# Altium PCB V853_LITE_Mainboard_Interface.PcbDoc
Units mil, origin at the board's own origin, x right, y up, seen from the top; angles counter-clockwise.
Board outline 3937.01 x 3385.83 mil, 4 copper layers (Top Layer, GND, PWR, Bottom Layer); 3 components, 131 nets, 196 pads, 0 vias.
Unrouted connection lines stored in the file: 39.
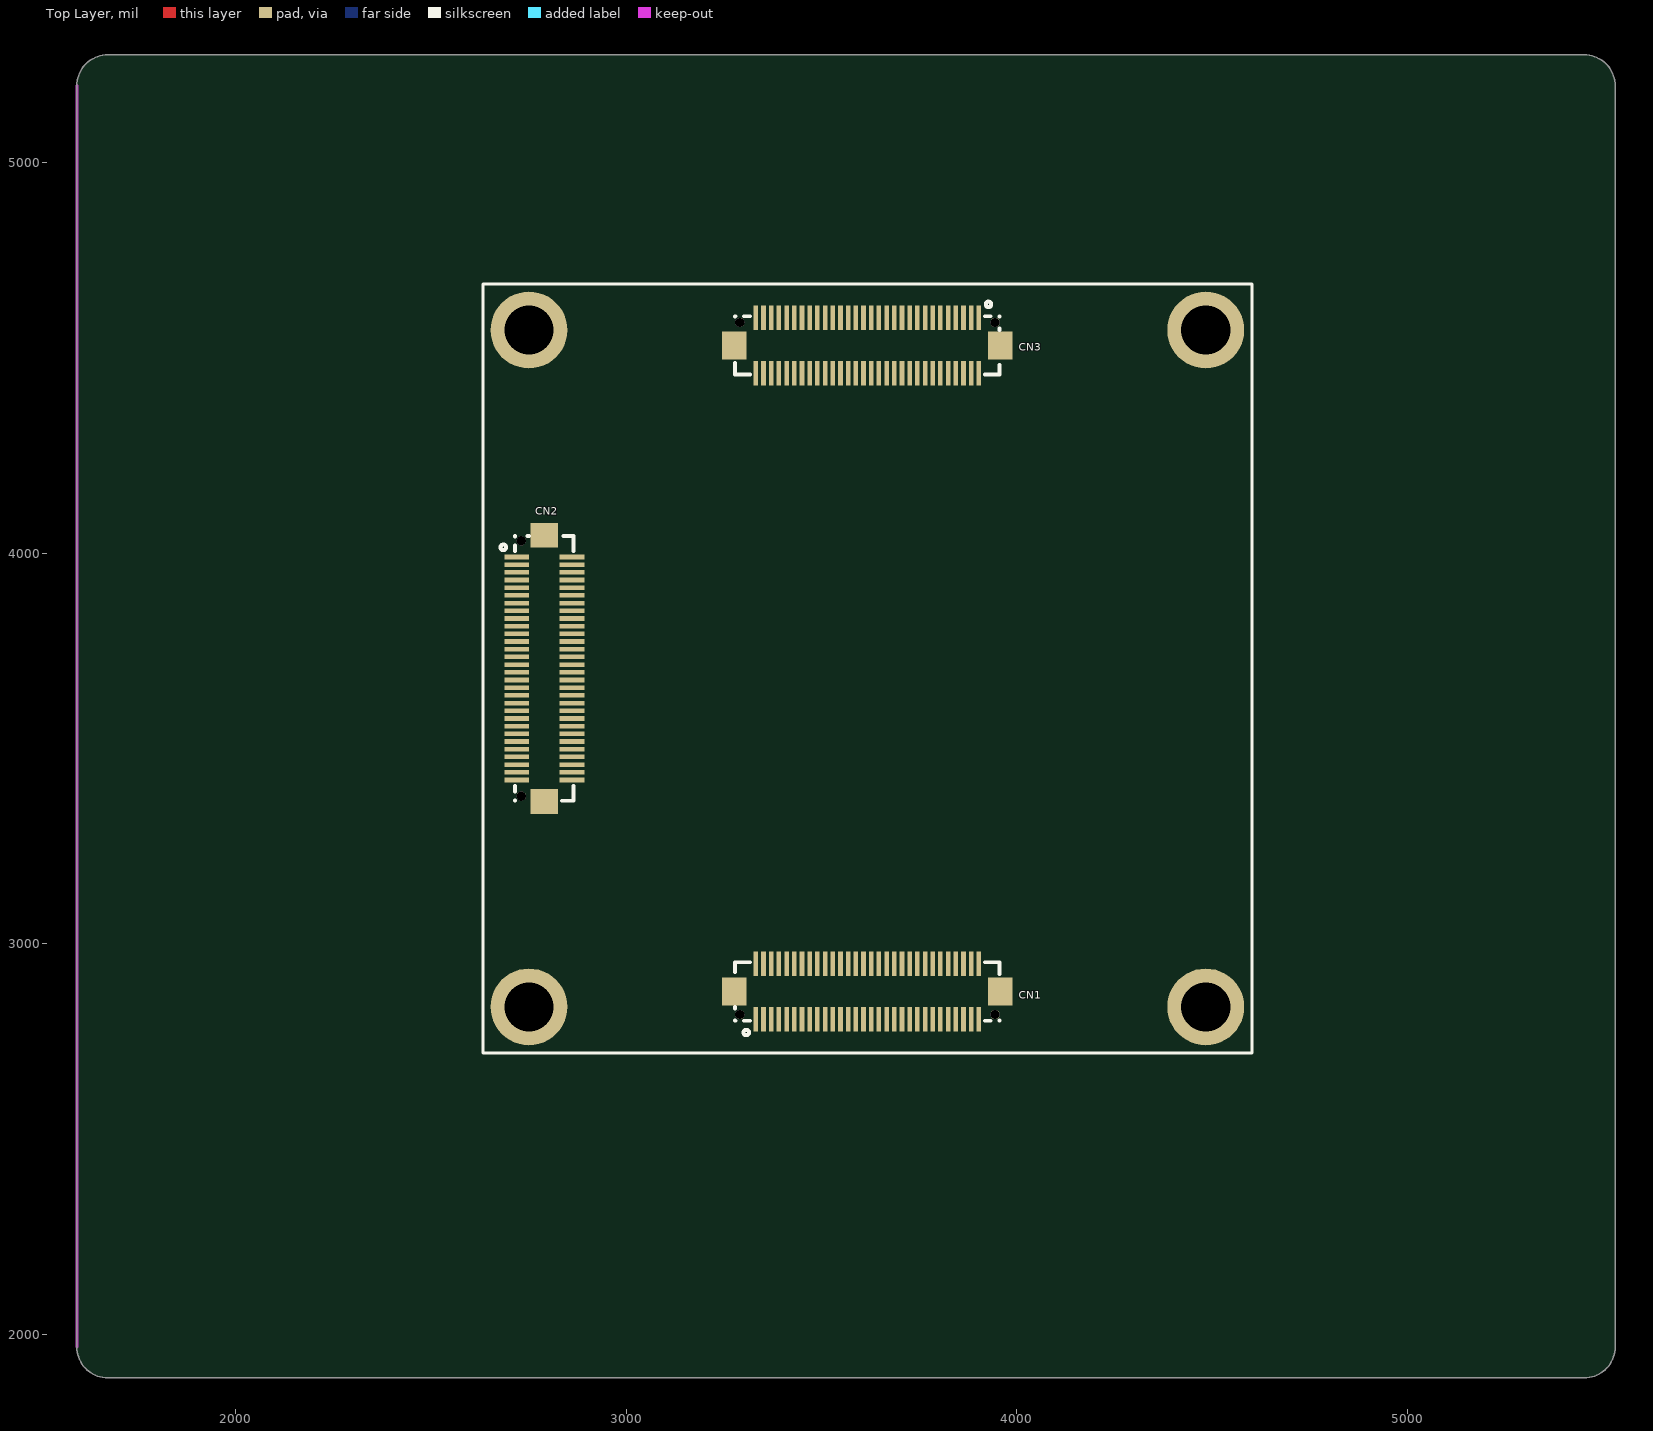
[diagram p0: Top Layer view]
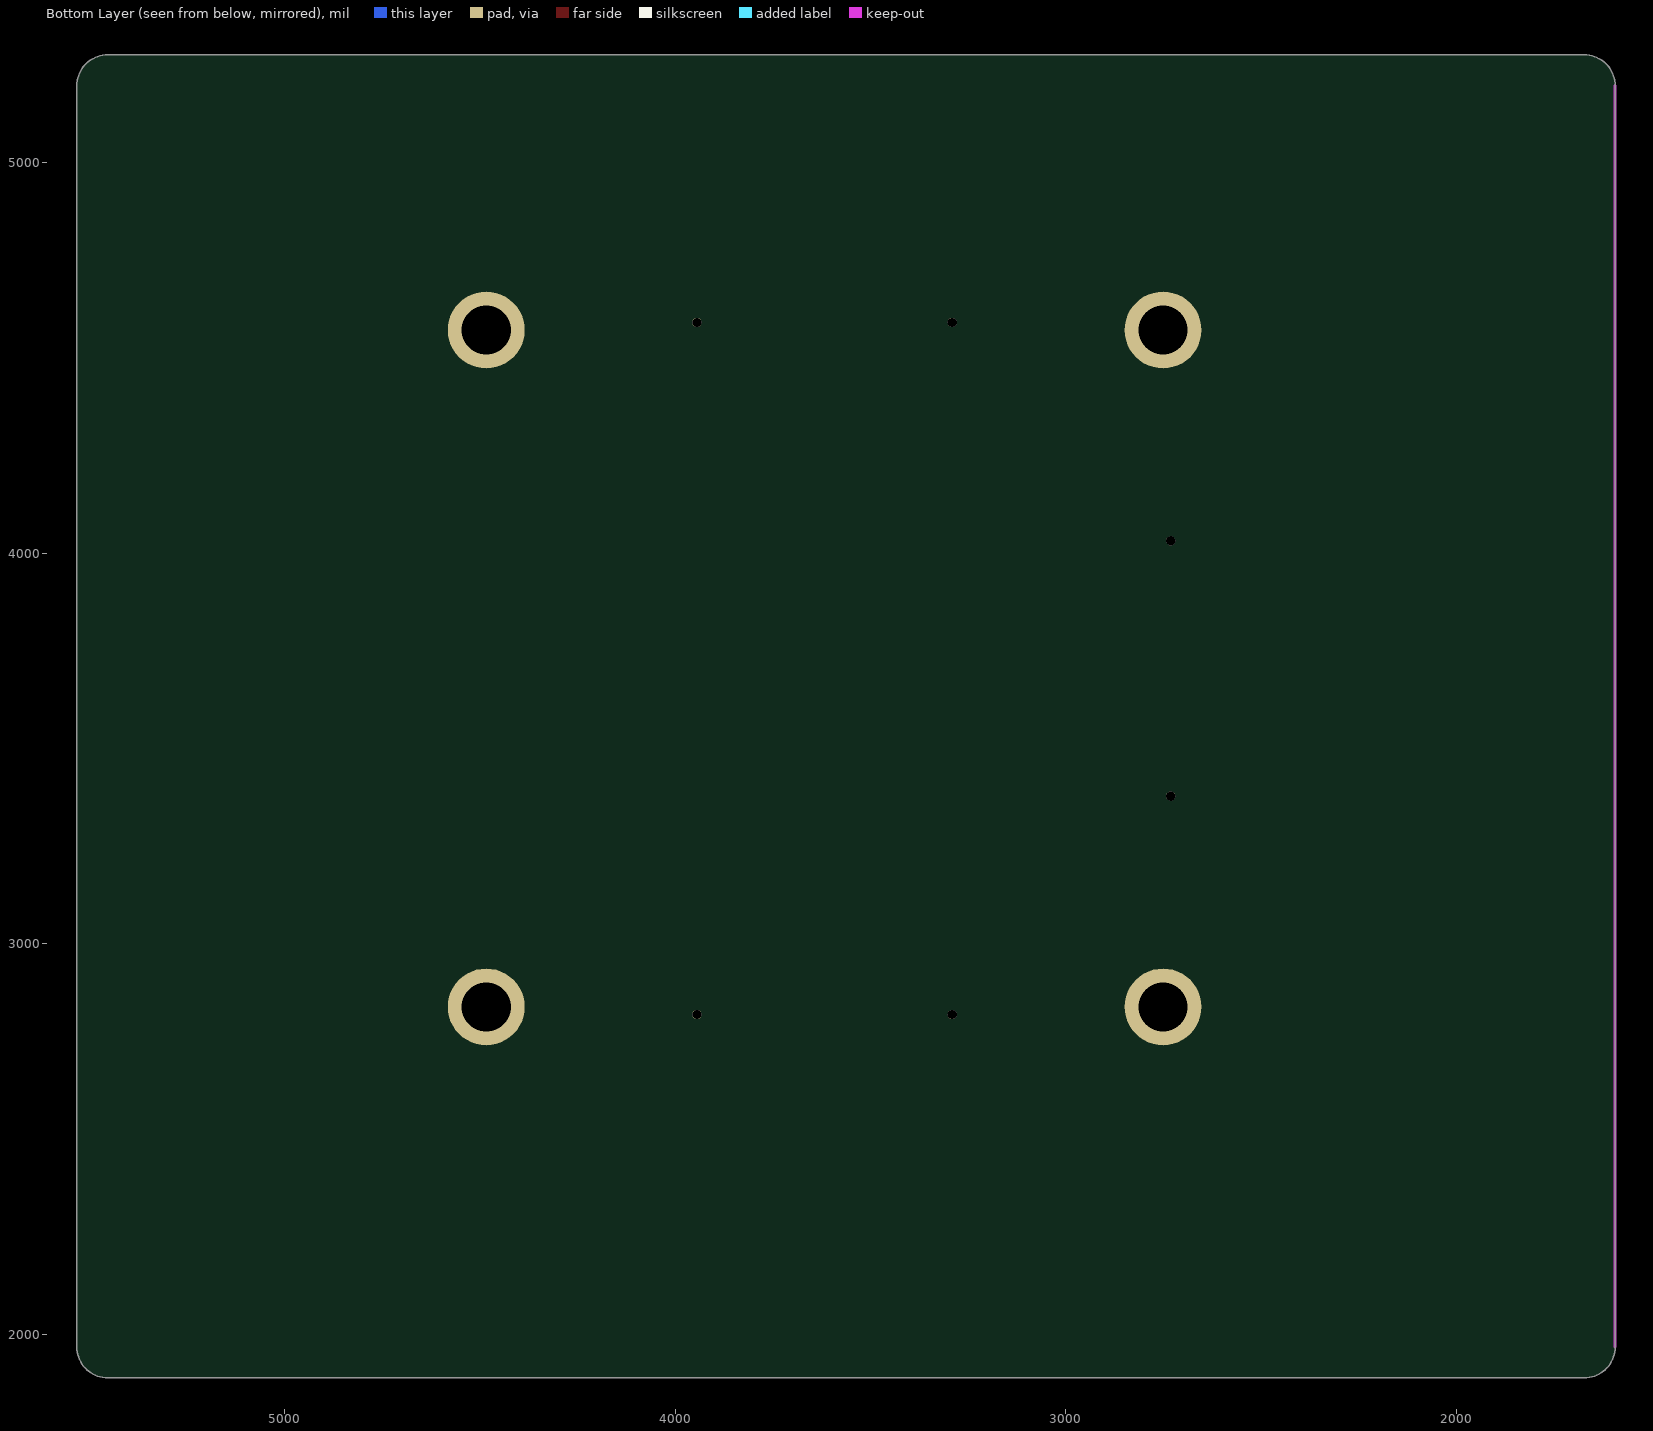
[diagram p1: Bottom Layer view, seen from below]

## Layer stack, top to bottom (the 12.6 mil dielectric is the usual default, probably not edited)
Top Solder: solder mask 0.4, Solder Resist, Dk 3.5
Top Layer: signal copper 1.4
Dielectric1: core 12.6, FR-4, Dk 4.8
GND: signal copper 1.4
Dielectric3: prepreg 12.6, FR-4, Dk 4.8
PWR: signal copper 1.4
Dielectric2: core 12.6, FR-4, Dk 4.8
Bottom Layer: signal copper 1.4
Bottom Solder: solder mask 0.4, Solder Resist, Dk 3.5

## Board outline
1594.49,1968.5 1594.49,5196.85 cw(c1673.23,5196.85) 1673.23,5275.59 5452.76,5275.59 cw(c5452.76,5196.85) 5531.5,5196.85 5531.5,1968.5 cw(c5452.76,1968.5) 5452.76,1889.76 1673.23,1889.76 cw(c1673.23,1968.5)

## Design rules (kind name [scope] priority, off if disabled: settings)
Clearance Clearance_1 [InPolygon] p1: gap=15
Clearance [All] p2: gap=5
ComponentClearance [All] p1 off: gap=10 collisioncheckmode=3 verticalgap=10 showdistances=FALSE
HoleSize [All] p1: absolutevalues=TRUE maxlimit=200 minlimit=1 maxpercent=80.000 minpercent=20.000
MinimumSolderMaskSliver [All] p1 off: minsoldermaskwidth=3
PolygonConnect PolygonConnect_1 [IsVia] p1: connectstyle=Direct reliefconductorwidth=10 reliefentries=4 polygonreliefangle="90 Angle" airgapwidth=10
PolygonConnect [All] p2: connectstyle=Relief reliefconductorwidth=20 reliefentries=4 polygonreliefangle="90 Angle" airgapwidth=20
RoutingVias [All] p1: holewidth=7.87 width=17.72 viastyle="Through Hole" minholewidth=7.87 minwidth=17.72 maxholewidth=7.87 maxwidth=17.72
SilkToSilkClearance [All] p1 off: silktosilkclearance=10
SilkToSolderMaskClearance [IsPad] p1 off: minsilkscreentomaskgap=3 clearancetoexposedcopper=TRUE
SolderMaskExpansion [All] p1: expansion=4
Width [All] p1: maxlimit=100 minlimit=5 preferedwidth=5 minimp=50.000000 maximp=50.000000 favimp=50.000000
25 further rules are at their usual default settings.

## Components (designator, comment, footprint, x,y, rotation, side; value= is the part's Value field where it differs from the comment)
CN1 "" CONN-SMD_60P-P0.50_XKB_X0502FVS-60AS-LPSN 3617.7,2878.38 r0 top locked
CN2 "" CONN-SMD_60P-P0.50_XKB_X0502FVS-60AS-LPSN 2790.93,3705.15 r270 top locked
CN3 "" CONN-SMD_60P-P0.50_XKB_X0502FVS-60AS-LPSN 3617.7,4531.93 r180 top locked

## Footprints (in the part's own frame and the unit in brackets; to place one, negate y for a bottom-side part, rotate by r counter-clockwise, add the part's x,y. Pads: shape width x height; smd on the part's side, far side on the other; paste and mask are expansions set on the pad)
CONN-SMD_60P-P0.50_XKB_X0502FVS-60AS-LPSN [mm]
  rect 0.3x1.6 smd paste+0 mask+0.05: 1(-7.25,-1.8) 2(-7.25,1.8) 3(-6.75,-1.8) 4(-6.75,1.8) 5(-6.25,-1.8) 6(-6.25,1.8) 7(-5.75,-1.8) 8(-5.75,1.8) 9(-5.25,-1.8) 10(-5.25,1.8) 11(-4.75,-1.8) 12(-4.75,1.8) 13(-4.25,-1.8) 14(-4.25,1.8) 15(-3.75,-1.8) 16(-3.75,1.8) 17(-3.25,-1.8) 18(-3.25,1.8) 19(-2.75,-1.8) 20(-2.75,1.8) 21(-2.25,-1.8) 22(-2.25,1.8) 23(-1.75,-1.8) 24(-1.75,1.8) 25(-1.25,-1.8) 26(-1.25,1.8) 27(-0.75,-1.8) 28(-0.75,1.8) 29(-0.25,-1.8) 30(-0.25,1.8) 31(0.25,-1.8) 32(0.25,1.8) 33(0.75,-1.8) 34(0.75,1.8) 35(1.25,-1.8) 36(1.25,1.8) 37(1.75,-1.8) 38(1.75,1.8) 39(2.25,-1.8) 40(2.25,1.8) 41(2.75,-1.8) 42(2.75,1.8) 43(3.25,-1.8) 44(3.25,1.8) 45(3.75,-1.8) 46(3.75,1.8) 47(4.25,-1.8) 48(4.25,1.8) 49(4.75,-1.8) 50(4.75,1.8) 51(5.25,-1.8) 52(5.25,1.8) 53(5.75,-1.8) 54(5.75,1.8) 55(6.25,-1.8) 56(6.25,1.8) 57(6.75,-1.8) 58(6.75,1.8) 59(7.25,-1.8) 60(7.25,1.8)
  rect 1.6x1.8 smd paste+0 mask+0.05: 61(8.65,0) 62(-8.65,0)
  round 0.6 hole 0.6 unplated paste+0: ""(-8.3,-1.5) ""(8.3,-1.5)
  silkscreen extent -8.6,-2.85 8.6,1.9

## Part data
CN1 CN2 CN3: library part X0502FVS-60AS-LPSN

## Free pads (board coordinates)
  round 196.85 hole 125.98: 0(2751.56,2839.01) 0(2751.56,4571.3) 0(4483.85,2839.01) 0(4483.85,4571.3)

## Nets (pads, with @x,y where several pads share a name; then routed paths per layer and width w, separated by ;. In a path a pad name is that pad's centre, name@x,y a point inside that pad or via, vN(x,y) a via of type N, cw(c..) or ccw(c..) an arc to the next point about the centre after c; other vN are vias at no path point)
ACIN: CN3.15 CN3.16 CN3.17 CN3.18 CN3.19 CN3.20
AP_RESET: CN1.55
AP_WAKE_BT_SOC: CN1.13
BT_RST_N_SOC: CN1.10
BT_UART_CTS: CN1.18
BT_UART_RTS: CN1.17
BT_UART_RX: CN1.16
BT_UART_TX: CN1.15
BT_WAKE_AP_SOC: CN1.14
CARD_PWROFF: CN3.34
CLK_FANOUT0: CN1.48
CPUX_TDI: CN3.30
CPUX_TDO: CN3.33
CPUX_TMS: CN3.35
CTP_INT: CN3.39
CTP_RST: CN3.38
CTP_SCL: CN3.43
CTP_SDA: CN3.40
DCDC1: CN1.54 CN1.56 CN1.58 CN1.60
DCXO_RFCLK: CN1.57
EPHY_LINK_LED: CN1.35
EPHY_RXN: CN1.38
EPHY_RXP: CN1.40
EPHY_SPD_LED: CN1.36
EPHY_TXN: CN1.37
EPHY_TXP: CN1.39
FEL: CN1.59
GND: CN1.11 CN1.12 CN1.21 CN1.22 CN1.31 CN1.32 CN1.41 CN1.42 CN2.11 CN2.12 CN2.21 CN2.22 CN2.31 CN2.32 CN2.41 CN2.42 CN3.11 CN3.12 CN3.21 CN3.22 CN3.31 CN3.32 CN3.41 CN3.42
GPADC0: CN3.49
GPADC1: CN3.50
GPADC2: CN3.51
GPADC3: CN3.52
LCD_RST: CN1.9
LINEOUTN: CN3.53
LINEOUTP: CN3.55
MBIAS: CN3.59
MICIN1N: CN3.60
MICIN1P: CN3.58
MICIN2N: CN3.56
MICIN2P: CN3.54
MIPI_CSI_CKN: CN2.25
MIPI_CSI_CKP: CN2.26
MIPI_CSI_D0N: CN2.19
MIPI_CSI_D0P: CN2.20
MIPI_CSI_D1N: CN2.24
MIPI_CSI_D1P: CN2.23
MIPI_CSI_D2N: CN2.18
MIPI_CSI_D2P: CN2.17
MIPI_CSI_D3N: CN2.16
MIPI_CSI_D3P: CN2.15
MIPI_CSI_MCLK0: CN2.10
MIPI_CSI_MCLK1: CN2.9
MIPI_CSI_PWDN0: CN2.3
MIPI_CSI_PWDN1: CN2.1
MIPI_CSI_RSTN0: CN2.4
MIPI_CSI_RSTN1: CN2.2
MIPI_DSI_CKN: CN2.43
MIPI_DSI_CKP: CN2.44
MIPI_DSI_D0N: CN2.37
MIPI_DSI_D0P: CN2.38
MIPI_DSI_D1N: CN2.39
MIPI_DSI_D1P: CN2.40
MIPI_DSI_D2N: CN2.45
MIPI_DSI_D2P: CN2.47
MIPI_DSI_D3N: CN2.48
MIPI_DSI_D3P: CN2.49
MIPIB_CSI_CKN: CN2.14
MIPIB_CSI_CKP: CN2.13
PA14: CN2.8
PA15: CN2.7
PA16: CN2.6
PA17: CN2.5
PA_SHDN: CN3.44
PD0: CN2.36
PD8: CN2.46
PD12: CN2.50
PD13: CN2.51
PD14: CN2.52
PD15: CN2.53
PD16: CN2.54
PD17: CN2.55
PD18: CN2.56
PD19: CN2.57
PD20: CN2.58
PD21: CN2.59
PD22: CN2.60
PE0: CN1.30
PE1: CN1.29
PE2: CN1.28
PE3: CN1.27
PE4: CN1.26
PE5: CN1.25
PE6: CN1.24
PE7: CN1.23
PE8: CN1.20
PE9: CN1.19
PH0: CN3.48
PH1: CN3.47
PH2: CN3.46
PH3: CN3.45
PH9: CN3.37
PH10: CN3.36
PH15: CN3.29
PI0: CN2.29
PI1: CN2.30
PI2: CN2.33
PI3: CN2.34
PI4: CN2.35
PS: CN3.5 CN3.6 CN3.7 CN3.8 CN3.9 CN3.10
PWRON_AXP2101: CN1.53
SDC0_CLK: CN1.4
SDC0_CMD: CN1.5
SDC0_D0: CN1.3
SDC0_D1: CN1.2
SDC0_D2: CN1.7
SDC0_D3: CN1.6
SDC0_DET: CN1.8
TS: CN3.28
TS_NTC: 
USB0_DM: CN2.28
USB0_DP: CN2.27
VBAT: CN3.23 CN3.24 CN3.25 CN3.26
VBAT2: CN3.27
VCC_3V3: 
WL_SDIO_CLK: CN1.49
WL_SDIO_CMD: CN1.50
WL_SDIO_D0: CN1.44
WL_SDIO_D1: CN1.45
WL_SDIO_D2: CN1.46
WL_SDIO_D3: CN1.47
WL_WAKE_AP: CN1.43
pads on no net: CN1. CN1.1 CN1.33 CN1.34 CN1.51 CN1.52 CN1.61 CN1.62 CN2. CN2.61 CN2.62 CN3. CN3.1 CN3.2 CN3.3 CN3.4 CN3.13 CN3.14 CN3.57 CN3.61 CN3.62

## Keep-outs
Keep-Out Layer:
  lines w7.99: 1594.49,1968.5 1594.49,5196.85

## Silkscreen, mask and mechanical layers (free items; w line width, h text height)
Top Overlay:
  lines w7.99: 2633.45,2720.9 4601.96,2720.9 4601.96,4689.41 2633.45,4689.41 2633.45,2720.9
Mechanical 13:
  lines w1: 2272.36,2351.89 2272.36,1666.85 2272.36,2351.89 ; 2272.36,2351.89 2315.67,2351.89 ; 2272.36,2351.89 2315.67,2351.89 ; 2315.67,2351.89 ccw(c2315.67,2377.48) 2341.26,2377.48 cw(c2315.67,2377.48) 2315.67,2351.89 ; 3750.71,1643.23 3760.55,1653.07 ; 3750.71,1643.23 2295.98,1643.23 3750.71,1643.23 ; 3750.71,1643.23 3760.55,1653.07 ; 3760.55,1653.07 3760.55,1781.02 ; 3760.55,1653.07 3760.55,1781.02 ; 3760.55,1781.02 cw(c3780.24,1781.02) 3799.92,1781.02 ; 3760.55,1781.02 cw(c3780.24,1781.02) 3799.92,1781.02 ; 3799.92,1653.07 3809.76,1643.23 ; 3799.92,1653.07 3799.92,1781.02 ; 3799.92,1653.07 3809.76,1643.23 ; 3799.92,1653.07 3799.92,1781.02 ; 3809.76,1643.23 4988.9,1643.23 ; 3809.76,1643.23 4988.9,1643.23 ; 4969.21,2351.89 cw(c4969.21,2377.48) 4943.62,2377.48 ccw(c4969.21,2377.48) 4969.21,2351.89 ; 4969.21,2351.89 5012.52,2351.89 ; 4969.21,2351.89 5012.52,2351.89 ; 4988.9,1643.23 5012.52,1666.85 ; 4988.9,1643.23 5012.52,1666.85 ; 5012.52,1666.85 5012.52,2351.89 ; 5012.52,1666.85 5012.52,2351.89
